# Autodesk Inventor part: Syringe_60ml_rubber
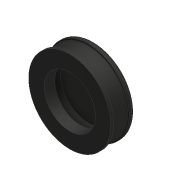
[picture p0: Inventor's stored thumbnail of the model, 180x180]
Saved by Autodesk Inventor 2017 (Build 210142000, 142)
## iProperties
Created: 2018-03
Part Number: Syringe_60ml_rubber
Material: Generic
Document SubType Name: Modeling
Designer: JK
Density: 1 g/cm^3
Appearance: Default
Title: C:/Users/Marco/Documents/Marco/3D printing/Syringe_60ml_rubber.step
Sending System: Autodesk Translation Framework v6.5.0.72
Preprocessor: ST-DEVELOPER v16.13
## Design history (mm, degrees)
feature "Body1"
body "Solid1"
